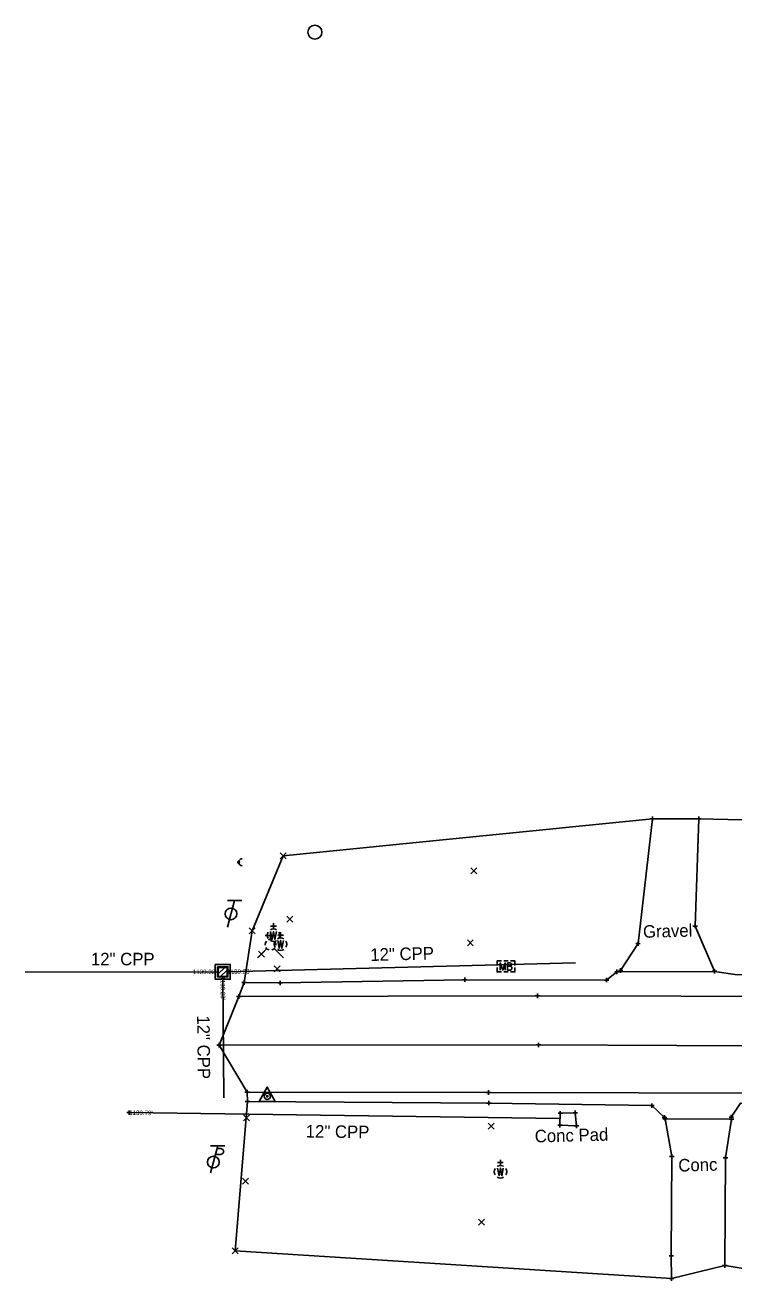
# Model space of a CAD drawing. Extents: x 146022 to 147632, y 437624 to 440659.
# Drawn here: x 146493.5 to 146651.9, y 438576.3 to 438856.8 of the extents above; entities that cross this region are included whole.
import ezdxf

# ---------------------------------------------------------------- set-up
doc = ezdxf.new("R2010")
doc.units = 0
for name, color, linetype in [('_CIVIL_CONSTRUCTION', 7, 'Continuous'), ('Default', 7, 'Continuous'), ('DR_P_Ditch', 7, 'Continuous'), ('DR_X_Storm_Sewer', 7, 'Continuous'), ('DR_X_Text', 7, 'Continuous'), ('DT_X_Contour_Major', 7, 'Continuous'), ('DT_X_Spot_Elev', 7, 'Continuous'), ('DT_X_Triangles', 7, 'Continuous'), ('PV_P_Curb', 7, 'Continuous'), ('PV_P_Joint', 7, 'Continuous'), ('RD_P_Anchor_Assembly', 7, 'Continuous'), ('RD_P_GR_Lt_Replaced', 7, 'Continuous'), ('RD_P_GR_Rt', 7, 'Continuous'), ('SC_Scratch1', 7, 'Continuous'), ('SC_Scratch3', 7, 'Continuous'), ('SV_X_Terrain_Boundary', 7, 'Continuous'), ('UT_X_Electric', 7, 'Continuous'), ('UT_X_Overhead_Cable_TV', 7, 'Continuous'), ('UT_X_Overhead_Electric', 7, 'Continuous')]:
    doc.layers.add(name, color=color, linetype=linetype)

msp = doc.modelspace()

# ---------------------------------------------------------------- linework, layer by layer
at = {"layer": '_CIVIL_CONSTRUCTION'}
for p, q in [((146550.44, 438670.55), (146551.77, 438671.88)), ((146550.44, 438671.88), (146551.77, 438670.55)), ((146593.07, 438667.21), (146594.41, 438668.55)), ((146593.07, 438668.55), (146594.41, 438667.21)), ((146551.93, 438656.44), (146553.26, 438657.77)), ((146551.93, 438657.77), (146553.26, 438656.44)), ((146543.55, 438653.81), (146544.88, 438655.14)), ((146543.55, 438655.14), (146544.88, 438653.81)), ((146592.31, 438651.11), (146593.64, 438652.45)), ((146592.31, 438652.45), (146593.64, 438651.11)), ((146545.63, 438648.57), (146546.96, 438649.91)), ((146545.63, 438649.91), (146546.96, 438648.57)), ((146549.13, 438645.33), (146550.47, 438646.66)), ((146549.13, 438646.66), (146550.47, 438645.33)), ((146542.29, 438612), (146543.63, 438613.34)), ((146542.29, 438613.34), (146543.63, 438612)), ((146596.96, 438610.18), (146598.29, 438611.51)), ((146596.96, 438611.51), (146598.29, 438610.18)), ((146542.03, 438597.85), (146543.36, 438599.18)), ((146542.03, 438599.18), (146543.36, 438597.85)), ((146594.81, 438588.73), (146596.14, 438590.07)), ((146594.81, 438590.07), (146596.14, 438588.73)), ((146539.73, 438582.3), (146541.06, 438583.64)), ((146539.73, 438583.64), (146541.06, 438582.3))]:
    msp.add_line(p, q, dxfattribs=at)
at = {"layer": 'Default'}
msp.add_circle((146558.22, 438855.23), 1.57, dxfattribs=at)
at = {"layer": 'DR_P_Ditch'}
msp.add_lwpolyline([(146613.08, 438613.71), (146616.42, 438613.84), (146616.71, 438610.88), (146613.01, 438611.02)], close=True, dxfattribs=at)
at = {"layer": 'DR_X_Storm_Sewer'}
for p, q in [((146538.64, 438645.3), (146616.48, 438647.31)), ((146536.64, 438645.3), (146493.45, 438645.24)), ((146537.64, 438644.3), (146537.88, 438617.18)), ((146516.7, 438613.86), (146613, 438612.57))]:
    msp.add_line(p, q, dxfattribs=at)
at = {"layer": 'DT_X_Contour_Major'}
for p, q in [((146536.5, 438606.41), (146534.89, 438600.41)), ((146538.1, 438606.41), (146534.9, 438606.41)), ((146536.34, 438605.81), (146537.19, 438605.81)), ((146535.99, 438604.53), (146537.19, 438604.53))]:
    msp.add_line(p, q, dxfattribs=at)
for centre, radius in [((146541.18, 438669.79), 0.2), ((146535.53, 438602.81), 1.3)]:
    msp.add_circle(centre, radius, dxfattribs=at)
for centre, radius, start, end in [((146541.98, 438669.79), 0.8, 90, 270), ((146537.2, 438605.17), 0.638, 268.8767, 91.1233)]:
    msp.add_arc(centre, radius, start, end, dxfattribs=at)
at = {"layer": 'DT_X_Spot_Elev'}
for p, q in [((146600.43, 438647.73), (146601.44, 438647.73)), ((146600.43, 438645.28), (146601.44, 438645.28)), ((146600.95, 438646.51), (146600.95, 438646.51))]:
    msp.add_line(p, q, dxfattribs=at)
for points in [[(146598.95, 438646.76), (146598.95, 438647.73), (146599.92, 438647.73)], [(146599.65, 438645.71), (146599.65, 438647.31), (146600.23, 438645.71), (146600.78, 438647.31), (146600.78, 438645.71)], [(146601.97, 438646.57), (146602.03, 438646.64), (146602.07, 438646.68), (146602.09, 438646.71), (146602.11, 438646.74), (146602.13, 438646.79), (146602.14, 438646.83), (146602.17, 438646.91), (146602.17, 438646.95), (146602.17, 438647), (146602.16, 438647.08), (146602.13, 438647.14), (146602.09, 438647.19), (146602.03, 438647.24), (146601.98, 438647.27), (146601.96, 438647.28), (146601.89, 438647.31), (146601.28, 438647.31), (146601.28, 438645.71), (146601.97, 438645.71), (146602.06, 438645.76), (146602.13, 438645.82), (146602.19, 438645.92), (146602.23, 438646.03), (146602.25, 438646.15), (146602.25, 438646.22), (146602.22, 438646.3), (146602.17, 438646.41), (146602.11, 438646.49), (146601.97, 438646.57), (146601.28, 438646.57)], [(146601.95, 438647.73), (146602.95, 438647.73), (146602.95, 438646.76)], [(146599.92, 438645.28), (146598.95, 438645.28), (146598.95, 438646.25)], [(146602.95, 438646.25), (146602.95, 438645.28), (146601.95, 438645.28)]]:
    msp.add_lwpolyline(points, dxfattribs=at)
at = {"layer": 'DT_X_Triangles'}
for p, q in [((146536.64, 438645.3), (146536.64, 438645.3)), ((146537.64, 438646.97), (146537.64, 438646.97)), ((146537.64, 438646.3), (146537.64, 438646.3)), ((146537.64, 438645.3), (146537.64, 438645.3)), ((146537.64, 438645.3), (146537.64, 438645.3)), ((146537.64, 438645.3), (146537.64, 438645.3)), ((146538.64, 438645.3), (146538.64, 438645.3)), ((146537.64, 438644.3), (146537.64, 438644.3)), ((146537.64, 438643.64), (146537.64, 438643.64))]:
    msp.add_line(p, q, dxfattribs=at)
at = {"layer": 'PV_P_Curb'}
msp.add_lwpolyline([(146760.89, 438628.57), (146670.03, 438628.72), (146608.22, 438628.98), (146536.84, 438628.93)], dxfattribs=at)
at = {"layer": 'PV_P_Joint'}
msp.add_lwpolyline([(146545.78, 438616.36), (146549.38, 438616.36), (146547.58, 438619.58)], close=True, dxfattribs=at)
for radius in [0.7, 0.16]:
    msp.add_circle((146547.58, 438617.52), radius, dxfattribs=at)
at = {"layer": 'RD_P_Anchor_Assembly'}
for p, q in [((146633.15, 438679.48), (146634.15, 438679.48)), ((146633.65, 438679.98), (146633.65, 438678.98)), ((146633.65, 438679.48), (146633.65, 438679.48)), ((146643.55, 438679.52), (146644.55, 438679.52)), ((146644.05, 438680.02), (146644.05, 438679.02)), ((146644.05, 438679.52), (146644.05, 438679.52)), ((146643.22, 438656.04), (146643.22, 438655.04)), ((146642.72, 438655.54), (146643.72, 438655.54)), ((146643.22, 438655.54), (146643.22, 438655.54)), ((146629.95, 438651.61), (146630.95, 438651.61)), ((146630.45, 438652.11), (146630.45, 438651.11)), ((146630.45, 438651.61), (146630.45, 438651.61)), ((146625.25, 438645.31), (146626.25, 438645.31)), ((146625.75, 438645.81), (146625.75, 438644.81)), ((146625.75, 438645.31), (146625.75, 438645.31)), ((146626.05, 438645.61), (146627.05, 438645.61)), ((146626.55, 438646.11), (146626.55, 438645.11)), ((146626.55, 438645.61), (146626.55, 438645.61)), ((146647.02, 438645.41), (146648.02, 438645.41)), ((146647.08, 438645.44), (146648.08, 438645.44)), ((146647.52, 438645.91), (146647.52, 438644.91)), ((146647.52, 438645.41), (146647.52, 438645.41)), ((146647.58, 438645.94), (146647.58, 438644.94)), ((146647.58, 438645.44), (146647.58, 438645.44)), ((146541.9, 438642.93), (146542.9, 438642.93)), ((146542.4, 438643.43), (146542.4, 438642.43)), ((146542.4, 438642.93), (146542.4, 438642.93)), ((146549.95, 438642.82), (146550.95, 438642.82)), ((146550.45, 438643.32), (146550.45, 438642.32)), ((146550.45, 438642.82), (146550.45, 438642.82)), ((146591.21, 438643.54), (146592.21, 438643.54)), ((146591.71, 438644.04), (146591.71, 438643.04)), ((146591.71, 438643.54), (146591.71, 438643.54)), ((146622.93, 438643.48), (146623.93, 438643.48)), ((146623.43, 438643.98), (146623.43, 438642.98)), ((146623.43, 438643.48), (146623.43, 438643.48)), ((146540.72, 438639.78), (146541.72, 438639.78)), ((146541.22, 438640.28), (146541.22, 438639.28)), ((146541.22, 438639.78), (146541.22, 438639.78)), ((146607.46, 438639.96), (146608.46, 438639.96)), ((146607.96, 438640.46), (146607.96, 438639.46)), ((146607.96, 438639.96), (146607.96, 438639.96)), ((146536.34, 438628.93), (146537.34, 438628.93)), ((146536.84, 438629.43), (146536.84, 438628.43)), ((146536.84, 438628.93), (146536.84, 438628.93)), ((146607.72, 438628.98), (146608.72, 438628.98)), ((146608.22, 438629.48), (146608.22, 438628.48)), ((146608.22, 438628.98), (146608.22, 438628.98)), ((146542.58, 438618.44), (146543.58, 438618.44)), ((146542.66, 438616.38), (146543.66, 438616.38)), ((146543.08, 438618.94), (146543.08, 438617.94)), ((146543.08, 438618.44), (146543.08, 438618.44)), ((146543.16, 438616.88), (146543.16, 438615.88)), ((146543.16, 438616.38), (146543.16, 438616.38)), ((146596.53, 438618.35), (146597.53, 438618.35)), ((146597.03, 438618.85), (146597.03, 438617.85)), ((146597.03, 438618.35), (146597.03, 438618.35)), ((146597.09, 438616.49), (146597.09, 438615.49)), ((146596.59, 438615.99), (146597.59, 438615.99)), ((146597.09, 438615.99), (146597.09, 438615.99)), ((146612.58, 438613.71), (146613.58, 438613.71)), ((146613.08, 438614.21), (146613.08, 438613.21)), ((146613.08, 438613.71), (146613.08, 438613.71)), ((146615.92, 438613.84), (146616.92, 438613.84)), ((146616.42, 438614.34), (146616.42, 438613.34)), ((146616.42, 438613.84), (146616.42, 438613.84)), ((146633.07, 438615.43), (146634.07, 438615.43)), ((146633.57, 438615.93), (146633.57, 438614.93)), ((146633.57, 438615.43), (146633.57, 438615.43)), ((146612.51, 438611.02), (146613.51, 438611.02)), ((146613.01, 438611.52), (146613.01, 438610.52)), ((146613.01, 438611.02), (146613.01, 438611.02)), ((146616.21, 438610.88), (146617.21, 438610.88)), ((146616.71, 438611.38), (146616.71, 438610.38)), ((146616.71, 438610.88), (146616.71, 438610.88)), ((146635.86, 438612.78), (146636.86, 438612.78)), ((146636.02, 438612.47), (146637.02, 438612.47)), ((146636.36, 438613.28), (146636.36, 438612.28)), ((146636.36, 438612.78), (146636.36, 438612.78)), ((146636.52, 438612.97), (146636.52, 438611.97)), ((146636.52, 438612.47), (146636.52, 438612.47)), ((146650.8, 438612.85), (146651.8, 438612.85)), ((146650.84, 438612.38), (146651.84, 438612.38)), ((146651.3, 438613.35), (146651.3, 438612.35)), ((146651.3, 438612.85), (146651.3, 438612.85)), ((146651.34, 438612.88), (146651.34, 438611.88)), ((146651.34, 438612.38), (146651.34, 438612.38)), ((146637.52, 438604.08), (146638.52, 438604.08)), ((146638.02, 438604.58), (146638.02, 438603.58)), ((146638.02, 438604.08), (146638.02, 438604.08)), ((146649.51, 438603.75), (146650.51, 438603.75)), ((146650.01, 438604.25), (146650.01, 438603.25)), ((146650.01, 438603.75), (146650.01, 438603.75)), ((146637.39, 438581.85), (146638.39, 438581.85)), ((146637.89, 438582.35), (146637.89, 438581.35)), ((146637.89, 438581.85), (146637.89, 438581.85)), ((146649.84, 438580.2), (146649.84, 438579.2)), ((146637.92, 438577.27), (146637.92, 438576.27)), ((146649.34, 438579.7), (146650.34, 438579.7)), ((146649.84, 438579.7), (146649.84, 438579.7)), ((146637.42, 438576.77), (146638.42, 438576.77)), ((146637.92, 438576.77), (146637.92, 438576.77))]:
    msp.add_line(p, q, dxfattribs=at)
at = {"layer": 'RD_P_GR_Lt_Replaced'}
msp.add_line((146550.45, 438642.82), (146542.4, 438642.93), dxfattribs=at)
for points in [[(146550.45, 438642.82), (146591.71, 438643.54), (146623.43, 438643.48), (146625.75, 438645.31), (146647.52, 438645.41), (146652.71, 438644.63), (146748.83, 438644.78), (146760.43, 438646.45), (146777.62, 438659.64), (146782.21, 438664.31), (146788.91, 438704.34), (146795.88, 438753.79)], [(146710.58, 438612.33), (146701.78, 438612.22), (146692.77, 438612.29), (146691.26, 438615.19), (146664.1, 438615.58), (146653.33, 438615.94), (146651.3, 438612.85), (146651.34, 438612.38), (146636.52, 438612.47), (146636.36, 438612.78), (146633.57, 438615.43), (146597.09, 438615.99), (146543.16, 438616.38)]]:
    msp.add_lwpolyline(points, dxfattribs=at)
at = {"layer": 'RD_P_GR_Rt'}
for p, q in [((146548.98, 438654.88), (146548.98, 438656.15)), ((146549.5, 438653.43), (146547.1, 438653.43)), ((146548.3, 438652.57), (146548.3, 438654.29)), ((146549.61, 438655.51), (146548.34, 438655.51)), ((146548.98, 438653.48), (146548.98, 438653.48)), ((146551.19, 438653.53), (146549.92, 438653.53)), ((146550.55, 438652.89), (146550.55, 438654.16)), ((146547.45, 438650.52), (146545.37, 438648.44)), ((146548.3, 438651.36), (146548.3, 438651.36)), ((146548.3, 438651.36), (146548.3, 438651.36)), ((146549.14, 438650.52), (146551.22, 438648.44)), ((146550.55, 438651.49), (146550.55, 438651.49)), ((146600.34, 438602.68), (146599.07, 438602.68)), ((146599.7, 438602.04), (146599.7, 438603.32)), ((146599.7, 438600.64), (146599.7, 438600.64))]:
    msp.add_line(p, q, dxfattribs=at)
for points in [[(146548.34, 438654.3), (146548.66, 438652.57), (146548.98, 438654.3), (146549.3, 438652.57), (146549.62, 438654.3)], [(146549.92, 438652.31), (146550.23, 438650.59), (146550.55, 438652.31), (146550.87, 438650.59), (146551.19, 438652.31)], [(146599.07, 438601.46), (146599.38, 438599.74), (146599.7, 438601.46), (146600.02, 438599.74), (146600.34, 438601.46)]]:
    msp.add_lwpolyline(points, dxfattribs=at)
for centre, radius, start, end in [((146548.98, 438653.48), 1.4, 150.0184, 209.9816), ((146548.98, 438653.48), 1.4, 60.0184, 120.0157), ((146550.55, 438651.49), 1.4, 60.0184, 120.0157), ((146548.98, 438653.48), 1.4, 330.0184, 29.9816), ((146548.3, 438651.36), 1.2, 140.021, 184.0629), ((146548.3, 438651.36), 1.2, 211.8788, 255.8479), ((146548.3, 438651.36), 1.2, 68.1395, 112.038), ((146548.98, 438653.48), 1.4, 239.9843, 299.9816), ((146548.3, 438651.36), 1.2, 283.8239, 329.9097), ((146550.55, 438651.49), 1.4, 150.0184, 209.9816), ((146548.3, 438651.36), 1.2, 356.0165, 39.9889), ((146550.55, 438651.49), 1.4, 239.9843, 299.9816), ((146550.55, 438651.49), 1.4, 330.0184, 29.9816), ((146599.7, 438600.65), 1.4, 150.0184, 209.9816), ((146599.7, 438600.65), 1.4, 60.0184, 120.0157), ((146599.7, 438600.65), 1.4, 330.0184, 29.9816), ((146599.7, 438600.65), 1.4, 239.9843, 299.9816)]:
    msp.add_arc(centre, radius, start, end, dxfattribs=at)
at = {"layer": 'SC_Scratch1'}
for points in [[(146626.55, 438645.61), (146630.45, 438651.61), (146633.65, 438679.48)], [(146644.05, 438679.52), (146643.22, 438655.54), (146647.58, 438645.44)], [(146649.84, 438579.7), (146650.01, 438603.75), (146651.34, 438612.38), (146636.52, 438612.47), (146638.02, 438604.08), (146637.89, 438581.85), (146637.92, 438576.77)]]:
    msp.add_lwpolyline(points, dxfattribs=at)
at = {"layer": 'SC_Scratch3'}
for points in [[(146750.71, 438639.45), (146672.12, 438639.82), (146607.96, 438639.96), (146541.22, 438639.78)], [(146543.08, 438618.44), (146597.03, 438618.35), (146664.15, 438618.22), (146719.64, 438618.19), (146788.82, 438617.8), (146882.32, 438617.3)]]:
    msp.add_lwpolyline(points, dxfattribs=at)
at = {"layer": 'SV_X_Terrain_Boundary'}
msp.add_lwpolyline([(146816.74, 438756.13), (146795.88, 438753.79), (146771.05, 438737.91), (146708.14, 438682.58), (146657.01, 438679.2), (146644.05, 438679.52), (146633.65, 438679.48), (146551.11, 438671.21), (146544.22, 438654.47), (146542.4, 438642.93), (146541.22, 438639.78), (146536.84, 438628.93), (146543.08, 438618.44), (146543.16, 438616.38), (146540.39, 438582.97), (146637.92, 438576.77), (146649.84, 438579.7), (146662.72, 438577.65), (146692.99, 438584.88), (146710.62, 438584.54), (146722.32, 438586.04), (146772.4, 438581.87), (146798.57, 438584.69), (146815.95, 438585.38)], dxfattribs=at)
at = {"layer": 'UT_X_Electric'}
for p, q in [((146536.49, 438644.69), (146538.25, 438646.45)), ((146536.49, 438645.82), (146537.12, 438646.45)), ((146537.09, 438644.16), (146538.78, 438645.85)), ((146538.22, 438644.16), (146538.78, 438644.72))]:
    msp.add_line(p, q, dxfattribs=at)
for points in [[(146535.97, 438646.97), (146539.3, 438646.97), (146539.3, 438643.64), (146535.97, 438643.64)], [(146536.49, 438646.45), (146538.78, 438646.45), (146538.78, 438644.16), (146536.49, 438644.16)], [(146536.64, 438646.3), (146538.64, 438646.3), (146538.64, 438644.3), (146536.64, 438644.3)]]:
    msp.add_lwpolyline(points, close=True, dxfattribs=at)
at = {"layer": 'UT_X_Overhead_Cable_TV'}
for p, q in [((146540.28, 438661.26), (146538.67, 438655.26)), ((146541.88, 438661.26), (146538.68, 438661.26))]:
    msp.add_line(p, q, dxfattribs=at)
msp.add_circle((146539.47, 438658.26), 1.3, dxfattribs=at)
at = {"layer": 'UT_X_Overhead_Electric'}
for p, q in [((146516.2, 438613.86), (146517.2, 438613.86)), ((146516.7, 438614.36), (146516.7, 438613.36)), ((146516.7, 438613.86), (146516.7, 438613.86))]:
    msp.add_line(p, q, dxfattribs=at)

# ---------------------------------------------------------------- texts
at = {"layer": 'DR_X_Text'}
for s, rotation, p in [('Gravel', 1.4771, (146631.6, 438652.9)), ('12" CPP', 1.4771, (146570.64, 438647.73)), ('12" CPP', 360, (146508.17, 438646.76)), ('12" CPP', 270.5379, (146531.9, 438635.57)), ('12" CPP', 359.2283, (146556.16, 438608.31)), ('Conc Pad', 1.4771, (146607.4, 438607.19)), ('Conc', 1.4771, (146639.49, 438600.68))]:
    msp.add_text(s, height=2.8, rotation=rotation, dxfattribs=at).set_placement(p)
at = {"layer": 'SC_Scratch1'}
for s, rotation, p in [("1139.32'", 0.0821, (146530.95, 438644.81)), ("1139.23'", 1.4771, (146538.65, 438644.8)), ("1139.23'", 270.5379, (146537.14, 438644.3)), ("1139.79'", 359.2283, (146516.7, 438613.36))]:
    msp.add_text(s, height=1, rotation=rotation, dxfattribs=at).set_placement(p)

doc.saveas('drawing.dxf')
